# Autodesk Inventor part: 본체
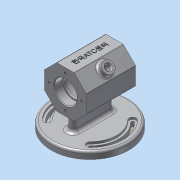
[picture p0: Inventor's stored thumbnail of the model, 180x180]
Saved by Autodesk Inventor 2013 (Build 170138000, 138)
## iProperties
Created: 2017-06
Part Number: 본체
Material: 알루미늄 6061
Document SubType Name: Modeling
Designer: dgall
Density: 1 g/cm^3
Author: dgall
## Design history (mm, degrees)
sketch "스케치1"
  geometry: L1 (-30, 12.426)-(-12.426, 30); L2 (-12.426, 30)-(12.426, 30); L3 (12.426, 30)-(30, 12.426); L4 (30, 12.426)-(30, -12.426); L5 (30, -12.426)-(12.426, -30); L6 (12.426, -30)-(-12.426, -30); L7 (-12.426, -30)-(-30, -12.426); L8 (-30, -12.426)-(-30, 12.426); 3 further points
  constraints: 16 end point, 1 coincident, 1 horizontal alignment, 1 midpoint, 17 other
  dimensions: "d1" = 30 distance from line of L8 point (0, 0)
extrude "돌출1" new body sketch "스케치1" distance "d2" = 70; taper "d3" = 0 deg
sketch "스케치2"
  geometry: L1 (30, 0)-(30, 70) reference; L2 (30, 70)-(12.426, 70) reference; L3 (12.426, 70)-(-12.426, 70) reference; L4 (-12.426, 70)-(-30, 70) reference; L5 (-30, 0)-(-30, 70) reference; L6 (-30, 0)-(-12.426, 0) reference; L7 (-12.426, 0)-(12.426, 0) reference; L8 (12.426, 0)-(30, 0) reference; L9 (0, 0)-(0, 70); L10 (16, 70)-(16, 58); L11 (16, 58)-(14, 58); L12 (14, 58)-(14, 55); L13 (14, 55)-(25, 55); L14 (25, 55)-(25, 15); L15 (25, 15)-(14, 15); L16 (14, 15)-(14, 12); L17 (14, 12)-(16, 12); L18 (16, 12)-(16, 0); L19 (16, 0)-(0, 0); L20 (16, 70)-(0, 70)
  constraints: 24 end point, 7 parallel, 2 collinear, 2 perpendicular, 2 point on line, 1 midpoint
  dimensions: "d4" = 12 distance of L10.start L10.end; "d6" = 32 diameter of L10 L9; "d7" = 3 distance of L11.end L12.end; "d8" = 28 diameter of L12 L9; "d9" = 40 distance of L13.end L14.end; "d10" = 50 diameter of L14 L9; "d11" = 3 distance of L15.end L16.end; "d12" = 28 diameter of L16 L9; "d13" = 32 diameter of L18 L9
revolve "회전1" sketch "스케치2" stored, may be unused: angle "d14" = 90 deg
fillet "모깎기1" dims "d15" = 0.3, "d16" = 3
chamfer "모따기1" distance "d17" = 1; stored, may be unused: second distance "d18" = 2, angle "d19" = 45 deg
sketch "스케치3"
  geometry: C1 r 17 at (0, 0) reference; 1 further point
  constraints: 1 vertical alignment
  dimensions: "d20" = 23 distance of C1.centre point (0, 23)
hole "구멍1" sketch "스케치3" at (0, 23) diameter "d21" = 3.459; stored, may be unused: countersink angle "d25" = 90 deg, drill point angle "d27" = 118 deg; dims "d22" = 8, "d23" = 4, "d24" = 2, "d26" = 10
node "작업 평면1"
node "작업 평면2"
sketch "스케치4"
  geometry: L1 (-30, 70)-(-12.426, 70) reference; L2 (-12.426, 70)-(12.426, 70) reference; L3 (12.426, 70)-(30, 70) reference; L4 (30, 0)-(30, 70) reference; L5 (-30, 0)-(-30, 70) reference; L6 (12.426, 0)-(-12.426, 0) reference; L7 (-12.426, 0)-(-30, 0) reference; L8 (30, 0)-(12.426, 0) reference; C1 r 55 at (0, 35); 3 further points
  constraints: 2 midpoint, 1 centre point, 1 horizontal alignment, 1 vertical alignment
  dimensions: "d32" = 110 diameter of C1
extrude "돌출2" join sketch "스케치4" distance "d33" = 10; taper "d34" = 0 deg
sketch "스케치5"
  geometry: L1 (-5, -24)-(-5, 24); L2 (5, 24)-(5, -24); C1 r 55 at (0, 0) reference; A1 r 5 centre (0, 24) between (5, 24) and (-5, 24); A2 r 5 centre (0, -24) between (-5, -24) and (5, -24); 3 further points
  constraints: 5 point on circle, 4 end point, 4 tangent, 2 centre point, 1 horizontal alignment, 1 midpoint, 1 parallel, 1 vertical, 1 vertical alignment
  dimensions: "d35" = 48 distance of A1.centre A2.centre; "d37" = 5 radius of A1
extrude "돌출3" join sketch "스케치5" stored distance "d38" = 10; taper "d39" = 0 deg
fillet "모깎기2" dims "d40" = 5
sketch "스케치6"
  geometry: L1 (-10, 24)-(-10, -24) reference; L2 (0, 0)-(-45.465, 45.465); L3 (0, 0)-(-47.277, -47.277); L4 (0, 0)-(-63.704, 0); C1 r 55 at (0, 0) reference; C2 r 43 at (0, 0); A1 r 38 centre (0, 0) between (-26.87, -26.87) and (-26.87, 26.87); A2 r 48 centre (0, 0) between (-33.941, -33.941) and (-33.941, 33.941); A3 r 5 centre (-30.406, -30.406) between (-33.941, -33.941) and (-26.87, -26.87); A4 r 5 centre (-30.406, 30.406) between (-26.87, 26.87) and (-33.941, 33.941); A5 r 48 centre (0, 0) between (-33.941, 33.941) and (-33.941, -33.941); A6 r 38 centre (0, 0) between (-26.87, 26.87) and (-26.87, -26.87); A7 r 2 centre (-30.406, -30.406) between (-31.82, -31.82) and (-28.991, -28.991); A8 r 2 centre (-30.406, 30.406) between (-28.991, 28.991) and (-31.82, 31.82); A9 r 41 centre (0, 0) between (-28.991, 28.991) and (-28.991, -28.991); A10 r 45 centre (0, 0) between (-31.82, 31.82) and (-31.82, -31.82); 1 further point
  constraints: 24 point on circle, 11 centre point, 8 point on line, 6 end point, 4 tangent, 3 coincident, 1 perpendicular
  dimensions: "d41" = 86 diameter of C2; "d42" = 90 deg angle of L2 L3; "d44" = 76 diameter of A1; "d45" = 96 diameter of A2; "d46" = 45 deg angle of L3 L4; "d47" = 5 radius of A3; "d48" = 5 radius of A4; "d49" = 2 radius of A7; "d50" = 2 radius of A8
extrude "돌출4" cut sketch "스케치6" distance "d51" = 3; taper "d52" = 0 deg
extrude "돌출5" cut sketch "스케치6" distance "d53" = 10; taper "d54" = 0 deg
fillet "모깎기3" dims "d55" = 3
sketch "스케치7"
  geometry: L1 (0, 0)-(-24.853, 0) reference; L2 (-24.853, 70)-(0, 70) reference; C1 r 8 at (-12.426, 35); C2 r 4 at (-12.426, 35); 2 further points
  constraints: 2 centre point, 1 coincident, 1 midpoint, 1 vertical alignment
  dimensions: "d56" = 16 diameter of C1; "d57" = 8 diameter of C2; "d58" = 35 distance from line of L2 C2.centre
extrude "돌출6" join sketch "스케치7" distance "d59" = 7; taper "d60" = 0 deg
extrude "돌출7" cut sketch "스케치7" stored distance "d61" = 7; taper "d62" = 0 deg
fillet "모깎기4" dims "d63" = 3
chamfer "모따기2" distance "d64" = 1; stored, may be unused: second distance "d65" = 2, angle "d66" = 45 deg
sketch "스케치8"
  geometry: L1 (24.853, -70)-(0, -70) reference; L2 (-17.574, 0)-(-17.574, -70) reference; 2 further points
  constraints: 1 other
  dimensions: "d67" = 35 distance from line of L1 point (12.426, -35); "d68" = 30 distance from line of L2 point (12.426, -35)
feature "엠보싱1" sketch "스케치8" dims "d69" = 0.5, "d70" = 0
fillet "모깎기5" dims "d71" = 1
node "솔리드1"
pattern_circular "원형 패턴1" dims angle "d29" = 360 deg
mirror "대칭1"
mirror "대칭2"
other parameters: "d31" = -62
